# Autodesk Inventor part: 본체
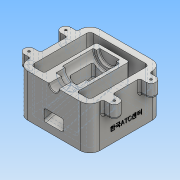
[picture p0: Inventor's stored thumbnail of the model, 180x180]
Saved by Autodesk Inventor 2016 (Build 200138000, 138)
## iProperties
Created: 2018-01
Part Number: 본체
Material: 알루미늄 6061
Document SubType Name: Modeling
Designer: Administrator
Density: 2.7 g/cm^3
Appearance: 알루미늄 - 평지
Mass: 995.207 g
Surface Area: 834.59 cm^2
Volume: 368.595 cm^3
Author: Administrator
## Parameters: d2 = 65 mm, d3 = 0, d4 = 27 mm, d6 = 7.5 mm, d8 = 0, d11 = 3.242 mm, d12 = 9 mm, d13 = 4 mm, d14 = 2 mm, d15 = 90 deg, d16 = 11 mm, d17 = 118 deg, d26 = 0, d31 = 15 mm, d32 = 32 mm, d35 = 19 mm, d36 = 14 mm, d37 = 47 mm, d38 = 5 mm, d39 = 90 deg, d41 = 18 mm, d43 = 105 deg, d45 = 5 mm, d47 = 11.061 mm, d48 = 0, d49 = 0, d50 = 5 mm, d51 = 5 mm, d52 = 5 mm, d53 = 5 mm, d54 = 19 mm, d55 = 0, d57 = 105 deg, d60 = 0, d61 = 15 mm, d65 = 55 mm, d66 = 0.5 mm, d67 = 0, d68 = 3 mm, d69 = 3 mm, d70 = 3 mm, d71 = 3 mm, d72 = 3 mm, d73 = 5 mm, d74 = 3 mm, d75 = 1 mm, d76 = 2 mm, d77 = 45 deg, d78 = 3 mm, d79 = 3 mm, d82 = 3 mm, d83 = 1 mm, d84 = 2.5 mm
